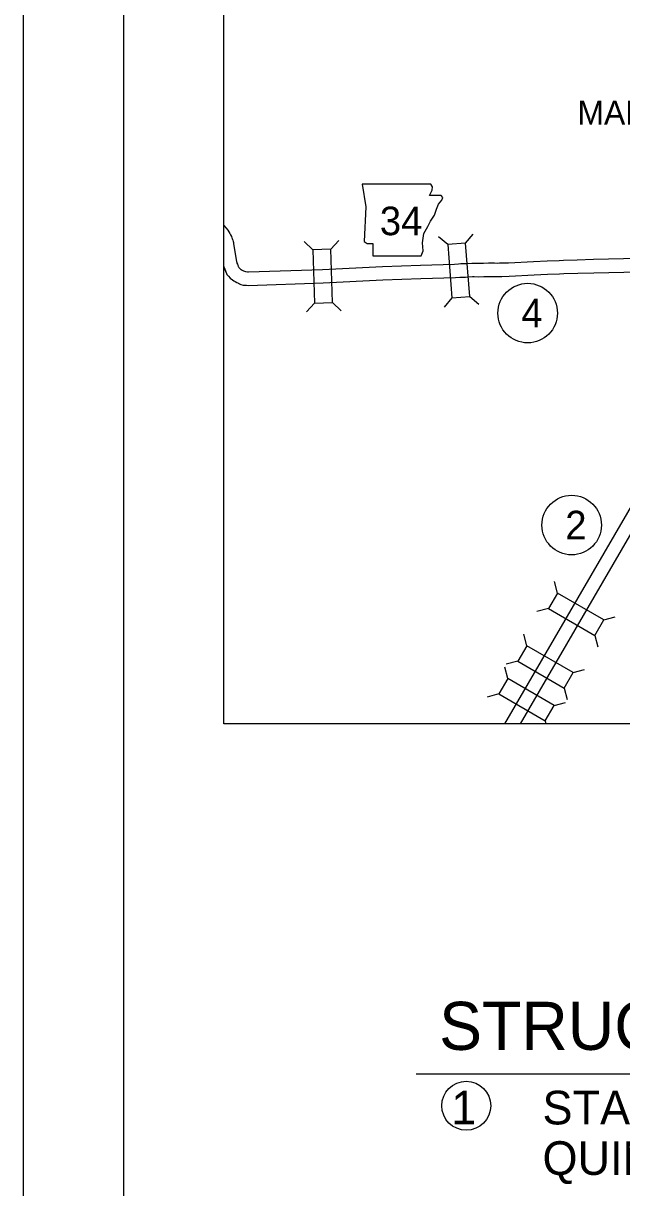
# Model space of a CAD drawing. Extents: x -0.3 to 2.65, y 0 to 1.9.
# Drawn here: x 0 to 0.1244, y 0.4452 to 0.6874 of the extents above; entities that cross this region are included whole.
import ezdxf

# ---------------------------------------------------------------- set-up
doc = ezdxf.new("R2010")
doc.units = 0
for name, color, linetype in [('DSN_DRFT_DNC', 7, 'Continuous'), ('Level 21', 7, 'Continuous'), ('Level 22', 7, 'Continuous'), ('Level 27', 7, 'Continuous'), ('Level 38', 7, 'Continuous'), ('Level 59', 7, 'Continuous'), ('Level 6', 7, 'Continuous'), ('SHET_Annotations', 7, 'Continuous'), ('SHET_Border-Lines', 7, 'Continuous'), ('SHET_Border-Text', 7, 'Continuous')]:
    doc.layers.add(name, color=color, linetype=linetype)

msp = doc.modelspace()

# ---------------------------------------------------------------- linework, layer by layer
at = {"layer": 'DSN_DRFT_DNC'}
msp.add_lwpolyline([(0.04167, 0.875), (0.34167, 0.875), (0.34167, 0.54167), (0.04167, 0.54167)], close=True, dxfattribs=at)
at = {"layer": 'Level 21'}
for points in [[(0.04167, 0.64532), (0.04215, 0.64476), (0.04248, 0.64433), (0.0427, 0.644), (0.0429, 0.64366), (0.04307, 0.64338), (0.04327, 0.64304), (0.04337, 0.64277), (0.04344, 0.6426), (0.0435, 0.64242), (0.04355, 0.64226), (0.04363, 0.64201), (0.04367, 0.64177), (0.04372, 0.6416), (0.04428, 0.63818), (0.04435, 0.63781), (0.04438, 0.63759), (0.04439, 0.63754), (0.04441, 0.63749), (0.04449, 0.63727), (0.04456, 0.63709), (0.04463, 0.6369), (0.04467, 0.63679), (0.04471, 0.63669), (0.04479, 0.63659), (0.04496, 0.63641), (0.04514, 0.63626), (0.0453, 0.63615), (0.04546, 0.63605), (0.04562, 0.63596), (0.04576, 0.6359), (0.04601, 0.6358), (0.04616, 0.63574), (0.04619, 0.63573), (0.04627, 0.63572), (0.04659, 0.63569), (0.04679, 0.63568), (0.06222, 0.63618), (0.07463, 0.63682), (0.08256, 0.63709), (0.08966, 0.63728), (0.09045, 0.63735), (0.09092, 0.6374), (0.0914, 0.63739), (0.09181, 0.63741), (0.09229, 0.63742)], [(0.09222, 0.63742), (0.09324, 0.6375), (0.09371, 0.63751), (0.09466, 0.63748), (0.09566, 0.6375), (0.09667, 0.63753), (0.09793, 0.63752), (0.09863, 0.6375), (0.09899, 0.63754), (0.09943, 0.63753), (0.10086, 0.63757), (0.10606, 0.63784), (0.10887, 0.63799), (0.11137, 0.63806), (0.11227, 0.63811), (0.11516, 0.63818), (0.11854, 0.63828), (0.12475, 0.63843), (0.14352, 0.63891), (0.1519, 0.63925)], [(0.04167, 0.6368), (0.04168, 0.63672), (0.0418, 0.63643), (0.04186, 0.6363), (0.04191, 0.63613), (0.042, 0.6359), (0.04206, 0.63574), (0.04216, 0.63551), (0.04234, 0.63515), (0.04266, 0.63475), (0.04302, 0.63437), (0.04345, 0.634), (0.04375, 0.6338), (0.04401, 0.63364), (0.04437, 0.63344), (0.04471, 0.63329), (0.04494, 0.6332), (0.04522, 0.63307), (0.04573, 0.63294), (0.04604, 0.63292), (0.04636, 0.63289), (0.04673, 0.63286), (0.06234, 0.63337), (0.07475, 0.63401), (0.08265, 0.63427), (0.08981, 0.63447), (0.09073, 0.63455), (0.09106, 0.63459), (0.09144, 0.63458), (0.09191, 0.6346), (0.09236, 0.63461)], [(0.09243, 0.63462), (0.09337, 0.63469), (0.09371, 0.63469), (0.09465, 0.63467), (0.09572, 0.63469), (0.09669, 0.63471), (0.09789, 0.63471), (0.09875, 0.63469), (0.0991, 0.63472), (0.09944, 0.63472), (0.10098, 0.63476), (0.10621, 0.63503), (0.10898, 0.63518), (0.11148, 0.63525), (0.11237, 0.6353), (0.11524, 0.63537), (0.11861, 0.63547), (0.12481, 0.63562), (0.14362, 0.6361), (0.15182, 0.63643)]]:
    msp.add_lwpolyline(points, dxfattribs=at)
at = {"layer": 'Level 22'}
msp.add_lwpolyline([(0.07046, 0.65394), (0.07117, 0.64918), (0.07086, 0.64197), (0.07149, 0.64157), (0.07268, 0.64157), (0.07268, 0.63903), (0.08267, 0.63903), (0.08315, 0.64006), (0.08299, 0.64173), (0.08323, 0.64363), (0.0841, 0.64514), (0.08466, 0.64625), (0.08545, 0.64744), (0.08592, 0.64871), (0.08632, 0.64974), (0.08703, 0.65061), (0.08719, 0.65117), (0.08688, 0.65156), (0.08442, 0.65156), (0.08497, 0.65267), (0.08505, 0.65339), (0.08472, 0.65394)], close=True, dxfattribs=at)
at = {"layer": 'Level 27'}
for points in [[(0.15185, 0.63643), (0.15192, 0.6322), (0.1519, 0.63195), (0.15185, 0.63182), (0.15181, 0.63169), (0.15177, 0.63161), (0.15171, 0.63148), (0.15167, 0.6314), (0.15157, 0.63122), (0.1515, 0.63106), (0.15141, 0.63092), (0.15128, 0.63065), (0.13318, 0.59874), (0.10003, 0.54167)], [(0.15466, 0.63665), (0.15473, 0.63214), (0.15471, 0.63175), (0.15468, 0.63141), (0.15458, 0.63107), (0.1545, 0.63088), (0.15443, 0.63063), (0.15431, 0.63039), (0.15424, 0.63025), (0.15416, 0.63008), (0.15408, 0.62994), (0.15399, 0.62975), (0.15389, 0.62959), (0.15377, 0.62934), (0.13562, 0.59734), (0.10328, 0.54167)]]:
    msp.add_lwpolyline(points, dxfattribs=at)
at = {"layer": 'Level 38'}
for p, q in [((0.06019, 0.64028), (0.05838, 0.64197)), ((0.0639, 0.6404), (0.06559, 0.6422)), ((0.08821, 0.64134), (0.08633, 0.64295)), ((0.09191, 0.64164), (0.09352, 0.64352)), ((0.0891, 0.63024), (0.0875, 0.62836)), ((0.09281, 0.63054), (0.09469, 0.62893)), ((0.06055, 0.62915), (0.05886, 0.62734)), ((0.06426, 0.62927), (0.06607, 0.62757)), ((0.11102, 0.56888), (0.11039, 0.57127)), ((0.10916, 0.56567), (0.10676, 0.56504)), ((0.12065, 0.56329), (0.12304, 0.56392)), ((0.10466, 0.55793), (0.10403, 0.56033)), ((0.11879, 0.56008), (0.11942, 0.55768)), ((0.1028, 0.55472), (0.1004, 0.55409)), ((0.10069, 0.5511), (0.10006, 0.55349)), ((0.11429, 0.55234), (0.11668, 0.55297)), ((0.09883, 0.54789), (0.09643, 0.54725)), ((0.11243, 0.54913), (0.11306, 0.54674)), ((0.11032, 0.5455), (0.11271, 0.54614)), ((0.10846, 0.54229), (0.10862, 0.54167))]:
    msp.add_line(p, q, dxfattribs=at)
for points in [[(0.06019, 0.64028), (0.06055, 0.62915), (0.06426, 0.62927), (0.0639, 0.6404)], [(0.09281, 0.63054), (0.09191, 0.64164), (0.08821, 0.64134), (0.0891, 0.63024)], [(0.10916, 0.56567), (0.11879, 0.56008), (0.12065, 0.56329), (0.11102, 0.56888)], [(0.11429, 0.55234), (0.10466, 0.55793), (0.1028, 0.55472), (0.11243, 0.54913)], [(0.11032, 0.5455), (0.10069, 0.5511), (0.09883, 0.54789), (0.10846, 0.54229)]]:
    msp.add_lwpolyline(points, close=True, dxfattribs=at)
at = {"layer": 'Level 59'}
for centre in [(0.10484, 0.6271), (0.11398, 0.58302)]:
    msp.add_circle(centre, 0.00619, dxfattribs=at)
at = {"layer": 'SHET_Annotations'}
msp.add_circle((0.09208, 0.46227), 0.00509, dxfattribs=at)
at = {"layer": 'SHET_Border-Lines'}
for points in [[(0, 0), (1.41667, 0), (1.41667, 0.91667), (0, 0.91667)], [(0.02083, 0.02083), (1.39583, 0.02083), (1.39583, 0.89583), (0.02083, 0.89583)]]:
    msp.add_lwpolyline(points, close=True, dxfattribs=at)
at = {"layer": 'SHET_Border-Text'}
msp.add_line((0.08167, 0.46888), (0.30167, 0.46888), dxfattribs=at)

# ---------------------------------------------------------------- texts
at = {"layer": 'Level 22'}
msp.add_text('34', height=0.00594, dxfattribs=at).set_placement((0.07411, 0.6433))
at = {"layer": 'Level 59'}
for s, p in [('4', (0.10352, 0.62413)), ('2', (0.11266, 0.58005))]:
    msp.add_text(s, height=0.00594, dxfattribs=at).set_placement(p)
at = {"layer": 'Level 6'}
msp.add_text('MARMADUKE', height=0.00495, dxfattribs=at).set_placement((0.11519, 0.66631))
at = {"layer": 'SHET_Annotations'}
for s, p in [('1', (0.08896, 0.45838)), ('STA. 112+05.00 CONSTRUCT', (0.10792, 0.45838)), ("QUINT. 12' X 12' X 52' R.C. BOX CULVERT", (0.10792, 0.44788))]:
    msp.add_text(s, height=0.007, dxfattribs=at).set_placement(p)
at = {"layer": 'SHET_Border-Text'}
msp.add_text('STRUCTURES OVER 20\'-0" SPAN', height=0.01, dxfattribs=at).set_placement((0.08643, 0.47388))

doc.saveas('drawing.dxf')
